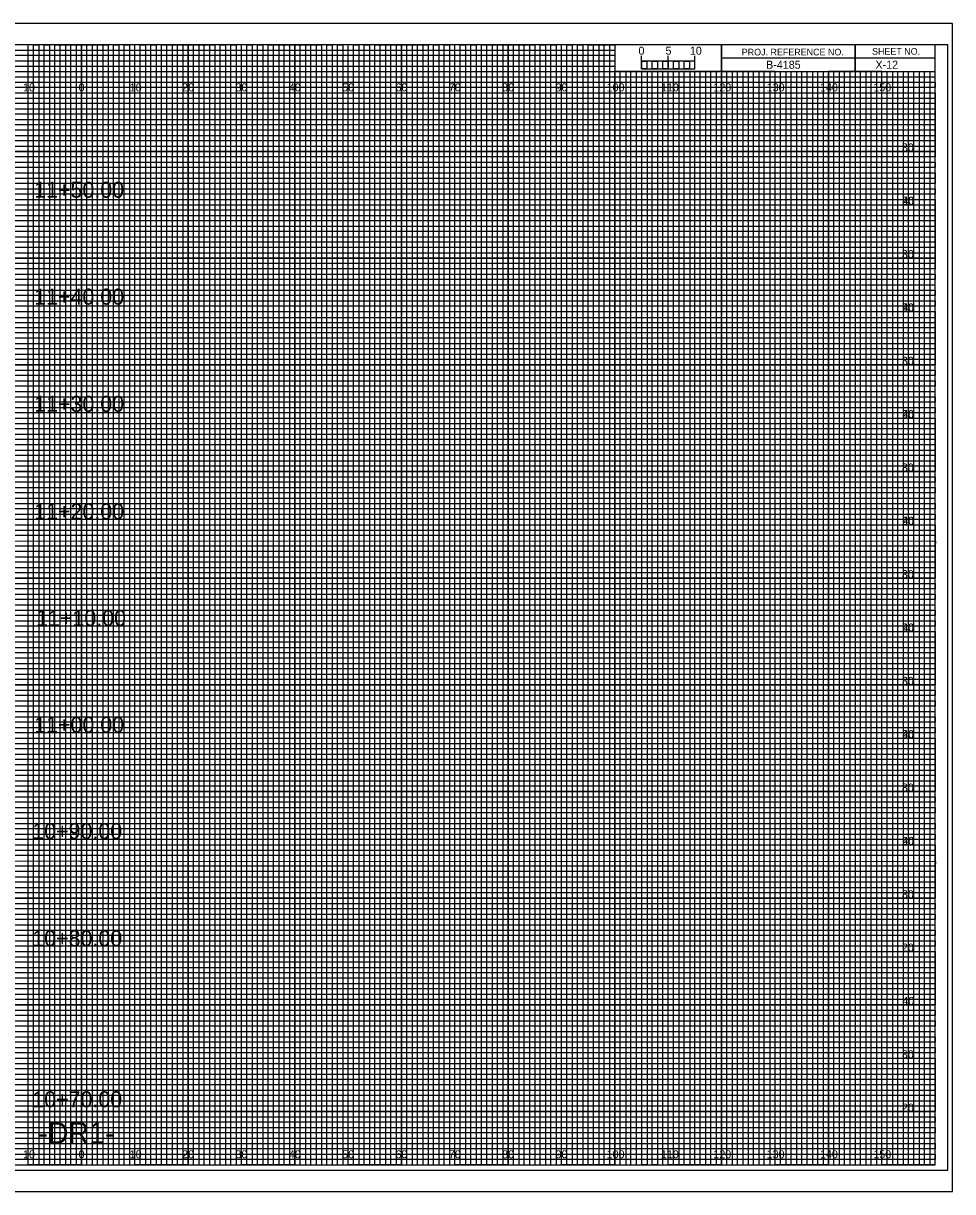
# Model space of a CAD drawing. Extents: x -13 to 323, y 215 to 434.
# Drawn here: x 149.1 to 323.3, y 215 to 434 of the extents above; entities that cross this region are included whole.
import ezdxf

# ---------------------------------------------------------------- set-up
doc = ezdxf.new("R2010")
doc.units = 0
for name, color, linetype in [('Prop XS Alignment Label', 7, 'Continuous'), ('Prop XS Bar Scale Labels', 7, 'Continuous'), ('Prop XS Elevation Labels', 7, 'Continuous'), ('Prop XS Offset Labels', 7, 'Continuous'), ('Prop XS Project Number', 7, 'Continuous'), ('Prop XS Sheet Number', 7, 'Continuous'), ('Prop XS Station Labels', 7, 'Continuous'), ('Sheet Cross Section CELL', 7, 'Continuous'), ('Sheet Cross Section Grid Major CELL', 7, 'Continuous'), ('Sheet Cross Section Grid Middle CELL', 7, 'Continuous'), ('Sheet Cross Section Grid Minor 1 CELL', 7, 'Continuous'), ('Sheet Cross Section Grid Minor 2 CELL', 7, 'Continuous'), ('Sheet Cross Section Scale CELL', 7, 'Continuous'), ('Sheet Cutting Line CELL', 7, 'Continuous'), ('Sheet DOT Grid CELL', 7, 'Continuous'), ('Sheet Plot Border Inside CELL', 7, 'Continuous'), ('Sheet Plot Border Outside CELL', 7, 'Continuous')]:
    doc.layers.add(name, color=color, linetype=linetype)

msp = doc.modelspace()

# ---------------------------------------------------------------- linework, layer by layer
at = {"layer": 'Sheet Cross Section CELL'}
for p, q in [((305, 430), (305, 425)), ((305, 425), (305, 430)), ((280, 427.5), (280, 425)), ((320, 427.49), (280, 427.49)), ((280, 425), (320, 425))]:
    msp.add_line(p, q, dxfattribs=at)
for points in [[(320, 430), (0, 430), (0, 220), (320, 220)], [(280, 430), (260, 430), (260, 425.03), (280, 425.03)], [(320, 430), (280, 430), (280, 425), (320, 425)]]:
    msp.add_lwpolyline(points, close=True, dxfattribs=at)
at = {"layer": 'Sheet Cross Section Grid Major CELL'}
for p, q in [((150, 430), (140, 430)), ((150, 220), (150, 430)), ((170, 430), (160, 430)), ((160, 430), (160, 220)), ((170, 220), (170, 430)), ((190, 430), (180, 430)), ((180, 430), (180, 220)), ((190, 220), (190, 430)), ((210, 430), (200, 430)), ((200, 430), (200, 220)), ((210, 220), (210, 430)), ((230, 430), (220, 430)), ((220, 430), (220, 220)), ((230, 220), (230, 430)), ((250, 430), (240, 430)), ((240, 430), (240, 220)), ((250, 220), (250, 430)), ((260, 430), (260, 220)), ((270, 220), (270, 425)), ((290, 425), (280, 425)), ((280, 425), (280, 220)), ((290, 220), (290, 425)), ((310, 425), (300, 425)), ((300, 425), (300, 220)), ((310, 220), (310, 425)), ((160, 220), (150, 220)), ((180, 220), (170, 220)), ((200, 220), (190, 220)), ((220, 220), (210, 220)), ((240, 220), (230, 220)), ((260, 220), (250, 220)), ((280, 220), (270, 220)), ((300, 220), (290, 220)), ((320, 220), (310, 220)), ((320, 220), (320, 220))]:
    msp.add_line(p, q, dxfattribs=at)
for points in [[(0, 420), (320, 420), (320, 410), (0, 410)], [(0, 400), (320, 400), (320, 390), (0, 390)], [(0, 380), (320, 380), (320, 370), (0, 370)], [(0, 360), (320, 360), (320, 350), (0, 350)], [(0, 340), (320, 340), (320, 330), (0, 330)], [(0, 320), (320, 320), (320, 310), (0, 310)], [(0, 300), (320, 300), (320, 290), (0, 290)], [(0, 280), (320, 280), (320, 270), (0, 270)], [(0, 260), (320, 260), (320, 250), (0, 250)], [(0, 240), (320, 240), (320, 230), (0, 230)]]:
    msp.add_lwpolyline(points, dxfattribs=at)
at = {"layer": 'Sheet Cross Section Grid Middle CELL'}
for points in [[(145, 220), (155, 220), (155, 430), (165, 430), (165, 220), (175, 220), (175, 430), (185, 430), (185, 220), (195, 220), (195, 430), (205, 430), (205, 220), (215, 220), (215, 430), (225, 430), (225, 220), (235, 220), (235, 430), (245, 430), (245, 220), (255, 220), (255, 430), (259.93, 430), (260, 430), (260, 425), (264.99, 425), (264.99, 220), (275, 220), (275, 425), (285, 425), (285, 220), (295, 220), (295, 425), (305, 425), (305, 220), (315, 220), (315, 425)], [(0, 425), (275, 425)], [(0, 405), (320, 405), (320, 415), (0, 415)], [(0, 385), (320, 385), (320, 395), (0, 395)], [(0, 365), (320, 365), (320, 375), (0, 375)], [(0, 345), (320, 345), (320, 355), (0, 355)], [(0, 325), (320, 325), (320, 335), (0, 335)], [(0, 305), (320, 305), (320, 315), (0, 315)], [(0, 285), (320, 285), (320, 295), (0, 295)], [(0, 265), (320, 265), (320, 275), (0, 275)], [(0, 245), (320, 245), (320, 255), (0, 255)], [(0, 225), (320, 225), (320, 235), (0, 235)]]:
    msp.add_lwpolyline(points, dxfattribs=at)
at = {"layer": 'Sheet Cross Section Grid Minor 1 CELL'}
for p, q in [((0, 429), (260, 429)), ((260, 427.98), (0, 427.98)), ((260, 429), (260, 427.98)), ((0, 427), (260, 427)), ((260, 425.89), (0, 425.89)), ((260, 427), (260, 425.89)), ((0, 424), (320, 424))]:
    msp.add_line(p, q, dxfattribs=at)
for points in [[(0, 423), (270, 423), (320, 423), (320, 422), (0, 422)], [(0, 421), (320, 421), (320, 419), (0, 419)], [(0, 418), (320, 418), (320, 417), (0, 416.98)], [(0, 416), (320, 416), (320, 414), (0, 414)], [(0, 413), (320, 413), (320, 412), (0, 412)], [(0, 411), (320, 411), (320, 409), (0, 409)], [(0, 408), (320, 408), (320, 407), (0, 407)], [(0, 406), (320, 406), (320, 404), (0, 404)], [(0, 403), (320, 403), (320, 402), (0, 402)], [(0, 401), (320, 401), (320, 399), (0, 399)], [(0, 398), (320, 398), (320, 397), (0, 397)], [(0, 396), (320, 396), (320, 393.95), (320, 393), (320, 392), (0, 392)], [(0, 394), (320, 394), (320, 393), (0, 393)], [(0, 391), (320, 391), (320, 389), (0, 389.03)], [(0, 389.03), (320, 389), (320, 388), (0, 388)], [(0, 387), (320, 387), (320, 386), (0, 386)], [(0, 384), (320, 384), (320, 383), (0, 383)], [(0, 382), (320, 382), (320, 381), (0, 381)], [(-0.07, 378.89), (320, 378.89), (320, 377.88), (-0.07, 377.88)], [(0, 377), (320, 377), (320, 376), (0, 376)], [(0, 374), (320, 374), (320, 373), (0, 373)], [(0, 372), (320, 372), (320, 371), (0, 371)], [(0, 369), (320, 369), (320, 368), (0, 368)], [(0, 367), (320, 367), (320, 366), (0, 366)], [(0, 364), (320, 364), (320, 363), (0, 363)], [(0, 362), (320, 362), (320, 361), (0, 361)], [(0, 359), (320, 359), (319.99, 357.98), (0, 358)], [(0, 357), (320, 357), (320, 356), (0, 356)], [(0, 354), (320, 354), (320, 353), (0, 353)], [(0, 352), (320, 352), (320, 351), (0, 351)], [(0, 349), (320, 349), (320, 348), (0, 348)], [(0, 347), (320, 347), (320, 346), (0, 346)], [(0, 344), (320, 344), (320, 343), (0, 343)], [(0, 342), (320, 342), (320, 341), (0, 341)], [(0, 339), (320, 339), (320, 338), (0, 338)], [(0, 336.99), (320.07, 336.91), (320, 336), (0, 336)], [(0, 334), (320, 334), (320, 333), (0, 333)], [(0, 332), (320, 332), (320, 331), (0, 331)], [(0, 329), (320, 329), (320, 328), (0, 328)], [(0, 327), (320, 327), (320, 326), (0, 326)], [(0, 324), (320, 324), (320, 323), (0, 323)], [(0, 322), (320, 322), (320, 321), (0, 321)], [(0, 319), (320, 319), (320, 318), (0, 318)], [(0, 317), (320, 317), (320, 316), (0, 316)], [(0, 314), (320, 314), (320, 313), (0, 313)], [(0, 312), (320, 312), (320, 311), (0, 311)], [(0, 309), (320, 309), (320, 308), (0, 308)], [(0, 307), (320, 307), (320, 306), (0, 306)], [(0, 304), (320, 304), (320, 303), (0, 303)], [(0, 302), (320, 302), (320, 301), (0, 301)], [(0, 299), (320, 299), (319.99, 297.98), (0, 298)], [(0, 297), (320, 297), (320, 296), (0, 296)], [(0, 294), (320, 294), (320, 293), (0, 293)], [(0, 292), (320, 292), (320, 291), (0, 291)], [(0, 289), (320, 289), (320, 288), (0, 288)], [(0, 287), (320, 287), (320, 286), (0, 286)], [(0, 284), (320, 284), (320, 283), (0, 283)], [(0, 282), (320, 282), (320, 281), (0, 281)], [(0, 279), (320, 279), (320, 278), (0, 278)], [(0, 276.99), (320.07, 276.91), (320, 276), (0, 276)], [(0, 274), (320, 274), (320, 273), (0, 273)], [(0, 272), (320, 272), (320, 271), (0, 271)], [(0, 269), (320, 269), (320, 268), (0, 268)], [(0, 267), (320, 267), (320, 266), (0, 266)], [(0, 264), (320, 264), (320, 263), (0, 263)], [(0, 262), (320, 262), (320, 261), (0, 261)], [(0, 259), (320, 259), (320, 258), (0, 258)], [(0, 257), (320, 257), (320, 256), (0, 256)], [(0, 254), (320, 254), (320, 253), (0, 253)], [(0, 252), (320, 252), (320, 251), (0, 251)], [(0, 249), (320, 249), (320, 248), (0, 248)], [(0, 247), (320, 247), (320, 246), (0, 246)], [(0, 244), (320, 244), (320, 243), (0, 243)], [(0, 242), (320, 242), (320, 241), (0, 241)], [(0, 239), (320, 239), (320, 238), (0, 238)], [(0, 237), (320, 237), (320, 236), (0, 236)], [(0, 234), (320, 234), (320, 233), (0, 233)], [(0, 232), (320, 232), (320, 231), (0, 231)], [(0, 229), (320, 229), (320, 228), (0, 228)], [(0, 227), (320, 227), (320, 226), (0, 226)], [(0, 224), (320, 224), (320, 223), (0, 223)], [(0, 222), (320, 222), (320, 221), (0, 221)]]:
    msp.add_lwpolyline(points, dxfattribs=at)
at = {"layer": 'Sheet Cross Section Grid Minor 2 CELL'}
for p, q in [((267, 425), (266.01, 425)), ((266.01, 425), (266.01, 220)), ((267, 220), (267, 425)), ((269, 425), (268, 425)), ((268, 425), (268, 220)), ((269, 220), (269, 425)), ((266.01, 220), (265, 220)), ((268, 220), (267, 220))]:
    msp.add_line(p, q, dxfattribs=at)
for points in [[(150, 220), (151, 220), (151, 430), (152, 430), (152, 220)], [(152, 220), (153, 220), (153, 430), (154, 430), (154, 220)], [(155, 220), (156, 220), (156, 430), (157, 430), (157, 220)], [(157, 220), (158, 220), (158, 430), (159, 430), (159, 220)], [(160, 220), (161, 220), (161, 430), (162, 430), (162, 220)], [(162, 220), (163, 220), (163, 430), (164, 430), (164, 220)], [(165, 220), (166, 220), (166, 430), (167, 430), (167, 220)], [(167, 220), (168, 220), (168, 430), (169, 430), (169, 220)], [(170, 220), (171, 220), (171, 430), (172, 430), (172, 220)], [(172, 220), (173, 220), (173, 430), (174, 430), (174, 220)], [(175, 220), (176, 220), (176, 430), (177, 430), (177, 220)], [(177, 220), (178, 220), (178, 430), (179, 430), (179, 220)], [(180, 220), (181, 220), (181, 430), (182, 430), (182, 220)], [(182, 220), (183, 220), (183, 430), (184, 430), (184, 220)], [(185, 220), (186, 220), (186, 430), (187, 430), (187, 220)], [(187, 220), (188, 220), (188, 430), (189, 430), (189, 220)], [(190, 220), (191, 220), (191, 430), (192, 430), (192, 220)], [(192, 220), (193, 220), (193, 430), (194, 430), (194, 220)], [(195, 220), (196, 220), (196, 430), (197, 430), (197, 220)], [(197, 220), (198, 220), (198, 430), (199, 430), (199, 220)], [(200, 220), (201, 220), (201, 430), (202, 430), (202, 220)], [(202, 220), (203, 220), (203, 430), (204, 430), (204, 220)], [(205, 220), (206, 220), (206, 430), (207, 430), (207, 220)], [(207, 220), (208, 220), (208, 430), (209, 430), (209, 220)], [(210, 220), (211, 220), (211, 430), (212, 430), (212, 220)], [(212, 220), (213, 220), (213, 430), (214, 430), (214, 220)], [(215, 220), (216, 220), (216, 430), (217, 430), (217, 220)], [(217, 220), (218, 220), (218, 430), (219, 430), (219, 220)], [(220, 220), (221, 220), (221, 430), (222, 430), (222, 220)], [(222, 220), (223, 220), (223, 430), (224, 430), (224, 220)], [(225, 220), (226, 220), (226, 430), (227, 430), (227, 220)], [(227, 220), (228, 220), (228, 430), (229, 430), (229, 220)], [(230, 220), (231, 220), (231, 430), (232, 430), (232, 220)], [(232, 220), (233, 220), (233, 430), (234, 430), (234, 220)], [(235, 220), (236, 220), (236, 430), (237, 430), (237, 220)], [(237, 220), (238, 220), (238, 430), (239, 430), (239, 220)], [(240, 220), (241, 220), (241, 430), (242, 430), (242, 220)], [(242, 220), (243, 220), (243, 430), (244, 430), (244, 220)], [(245, 220), (246, 220), (246, 430), (247, 430), (247, 220)], [(247, 220), (248, 220), (248, 430), (249, 430), (249, 220)], [(250, 220), (251, 220), (251, 430), (252, 430), (252, 220)], [(252, 220), (253, 220), (253, 430), (254, 430), (254, 220)], [(255, 220), (256, 220), (256, 430), (257, 430), (257, 220)], [(257, 220), (258, 220), (258, 430), (259, 430), (259, 220)], [(260, 220), (261, 220), (261, 425), (262.02, 425), (262.02, 220)], [(262, 220), (263, 220), (263, 425), (263.99, 425), (263.99, 220)], [(270, 220), (270.98, 220), (270.98, 425), (272, 425), (272, 220)], [(272, 220), (273, 220), (273, 425), (274.05, 425), (274.05, 220)], [(275, 220), (276, 220), (276, 425), (277, 425), (277, 220)], [(277, 220), (278, 220), (278, 425), (279, 425), (279, 220)], [(280, 220), (281, 220), (281, 425), (282, 425), (282, 220)], [(282, 220), (283, 220), (283, 425), (284, 425), (284, 220)], [(285, 220), (286, 220), (286, 425), (287, 425), (287, 220)], [(287, 220), (288, 220), (288, 425), (289, 425), (289, 220)], [(290, 220), (291, 220), (291, 425), (292, 425), (292, 220)], [(292, 220), (293, 220), (293, 425), (294, 425), (294, 220)], [(295, 220), (296, 220), (296, 425), (297, 425), (297, 220)], [(297, 220), (298, 220), (298, 425), (299, 425), (299, 220)], [(300, 220), (301, 220), (301, 425), (302, 425), (302, 220)], [(302, 220), (303, 220), (303, 425), (304, 425), (304, 220)], [(305, 220), (306, 220), (306, 425), (307, 425), (307, 220)], [(307, 220), (308, 220), (308, 425), (309, 425), (309, 220)], [(310, 220), (311, 220), (311, 425), (312, 425), (312, 220)], [(312, 220), (313, 220), (313, 425), (314, 425), (314, 220)], [(315, 220), (316, 220), (316, 425), (317, 425), (317, 220)], [(317, 220), (318, 220), (318, 425), (319, 425), (319, 220)]]:
    msp.add_lwpolyline(points, dxfattribs=at)
at = {"layer": 'Sheet Cross Section Scale CELL'}
for p, q in [((265, 425.49), (265, 427.9)), ((265, 426.9), (265, 427.9)), ((270, 425.49), (270, 427.9)), ((275, 425.49), (275, 427.9)), ((275, 426.9), (275, 427.9))]:
    msp.add_line(p, q, dxfattribs=at)
for points in [[(275, 426.9), (265, 426.9), (265, 425.49), (275, 425.49)], [(265, 426.9), (266, 426.9), (266, 425.49), (265, 425.49)], [(267, 426.9), (268, 426.9), (268, 425.49), (267, 425.49)], [(269, 426.9), (270, 426.9), (270, 425.49), (269, 425.49)], [(271, 426.9), (272, 426.9), (272, 425.49), (271, 425.49)], [(273, 426.9), (274, 426.9), (274, 425.49), (273, 425.49)]]:
    msp.add_lwpolyline(points, close=True, dxfattribs=at)
at = {"layer": 'Sheet Cutting Line CELL'}
for p, q in [((323.3, 434), (-13.4, 434)), ((-13.4, 215), (323.3, 215))]:
    msp.add_line(p, q, dxfattribs=at)
at = {"layer": 'Sheet DOT Grid CELL'}
for p, q in [((150, 220), (150, 430)), ((160, 220), (160, 430)), ((170, 220), (170, 430)), ((180, 220), (180, 430)), ((190, 220), (190, 430)), ((200, 220), (200, 430)), ((210, 220), (210, 430)), ((220, 220), (220, 430)), ((230, 220), (230, 430)), ((240, 220), (240, 430)), ((250, 220), (250, 430)), ((260, 220), (260, 424.69)), ((270, 220), (270, 424.69)), ((280, 220), (280, 424.69)), ((290, 220), (290, 424.69)), ((300, 220), (300, 424.69)), ((310, 220), (310, 424.69)), ((0, 420), (320, 420)), ((0, 410), (320, 410)), ((0, 400), (320, 400)), ((0, 390), (320, 390)), ((0, 380), (320, 380)), ((0, 370), (320, 370)), ((0, 360), (320, 360)), ((0, 350), (320, 350)), ((0, 340), (320, 340)), ((0, 330), (320, 330)), ((0, 320), (320, 320)), ((0, 310), (320, 310)), ((0, 300), (320, 300)), ((0, 290), (320, 290)), ((0, 280), (320, 280)), ((0, 270), (320, 270)), ((0, 260), (320, 260)), ((0, 250), (320, 250)), ((0, 240), (320, 240)), ((0, 230), (320, 230))]:
    msp.add_line(p, q, dxfattribs=at)
at = {"layer": 'Sheet Plot Border Inside CELL'}
msp.add_lwpolyline([(-10.8, 219), (322.4, 219), (322.4, 430), (-10.8, 430)], close=True, dxfattribs=at)
at = {"layer": 'Sheet Plot Border Outside CELL'}
msp.add_lwpolyline([(-13.4, 215), (323.3, 215), (323.3, 434), (-13.4, 434)], close=True, dxfattribs=at)

# ---------------------------------------------------------------- texts
at = {"layer": 'Prop XS Alignment Label'}
msp.add_text('-DR1-', height=4, dxfattribs=at).set_placement((151.91, 224))
at = {"layer": 'Prop XS Bar Scale Labels'}
for s, p in [('5', (269.47, 428.12)), ('10', (274.04, 428.12))]:
    msp.add_text(s, height=1.5, dxfattribs=at).set_placement(p)
at = {"layer": 'Prop XS Elevation Labels'}
for s, p in [('30', (313.78, 410)), ('20', (313.8, 400)), ('40', (313.87, 400)), ('30', (313.78, 390)), ('20', (313.8, 380)), ('40', (313.87, 380)), ('30', (313.78, 370)), ('20', (313.8, 360)), ('40', (313.87, 360)), ('30', (313.78, 350)), ('20', (313.8, 340)), ('40', (313.87, 340)), ('30', (313.78, 330)), ('20', (313.8, 320)), ('40', (313.87, 320)), ('30', (313.78, 310)), ('20', (313.8, 300)), ('40', (313.87, 300)), ('30', (313.78, 290)), ('20', (313.8, 280)), ('40', (313.87, 280)), ('30', (313.78, 270)), ('20', (313.8, 260)), ('40', (313.87, 250)), ('30', (313.78, 240)), ('20', (313.8, 230))]:
    msp.add_text(s, height=1.5, dxfattribs=at).set_placement(p)
at = {"layer": 'Prop XS Offset Labels'}
for s, p in [('10', (149.04, 421.25)), ('0', (159.45, 421.25)), ('0', (159.45, 421.25)), ('10', (169.04, 421.25)), ('20', (178.86, 421.25)), ('30', (188.86, 421.25)), ('40', (198.86, 421.25)), ('50', (208.86, 421.25)), ('60', (218.86, 421.25)), ('70', (228.86, 421.25)), ('80', (238.86, 421.25)), ('90', (248.86, 421.25)), ('100', (258.44, 421.25)), ('110', (268.62, 421.25)), ('120', (278.44, 421.25)), ('130', (288.44, 421.25)), ('140', (298.44, 421.25)), ('150', (308.44, 421.25)), ('10', (149.04, 221.25)), ('0', (159.45, 221.25)), ('0', (159.45, 221.25)), ('10', (169.04, 221.25)), ('20', (178.86, 221.25)), ('30', (188.86, 221.25)), ('40', (198.86, 221.25)), ('50', (208.86, 221.25)), ('60', (218.86, 221.25)), ('70', (228.86, 221.25)), ('80', (238.86, 221.25)), ('90', (248.86, 221.25)), ('100', (258.44, 221.25)), ('110', (268.62, 221.25)), ('120', (278.44, 221.25)), ('130', (288.44, 221.25)), ('140', (298.44, 221.25)), ('150', (308.44, 221.25))]:
    msp.add_text(s, height=1.5, dxfattribs=at).set_placement(p)
at = {"layer": 'Prop XS Project Number'}
msp.add_text('B-4185', height=1.5, dxfattribs=at).set_placement((288.34, 425.5))
at = {"layer": 'Prop XS Sheet Number'}
msp.add_text('X-12', height=1.5, dxfattribs=at).set_placement((308.83, 425.5))
at = {"layer": 'Prop XS Station Labels'}
for s, p in [('11+50.00', (151.13, 401.31)), ('11+40.00', (151.13, 381.27)), ('11+30.00', (151.13, 361.18)), ('11+20.00', (151.13, 341.02)), ('11+10.00', (151.49, 321.03)), ('11+00.00', (151.13, 301.03)), ('10+90.00', (150.77, 281.09)), ('10+80.00', (150.77, 260.99)), ('10+70.00', (150.77, 230.81))]:
    msp.add_text(s, height=3, dxfattribs=at).set_placement(p)
at = {"layer": 'Sheet Cross Section CELL'}
for s, p in [('PROJ. REFERENCE NO.', (283.77, 427.99)), ('SHEET NO.', (308.19, 428.12))]:
    msp.add_text(s, height=1.25, dxfattribs=at).set_placement(p)
at = {"layer": 'Sheet Cross Section Scale CELL'}
msp.add_text('0', height=1.5, dxfattribs=at).set_placement((264.41, 428.12))

doc.saveas('drawing.dxf')
